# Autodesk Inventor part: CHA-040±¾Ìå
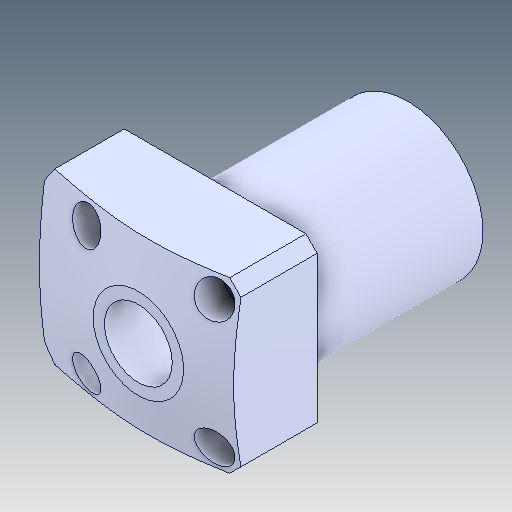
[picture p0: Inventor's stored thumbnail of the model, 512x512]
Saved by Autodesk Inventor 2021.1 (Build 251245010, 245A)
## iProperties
Created: 2021-05
Part Number: CHA-040±¾Ìå
Material: Ogólny
Document SubType Name: Modeling
Designer: user
Density: 1 g/cm^3
Appearance: Domyślna
Author: user
Revision Number: ÈÎºÎ
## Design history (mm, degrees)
feature "µ¹½Ç1"
node "Bryła1"
